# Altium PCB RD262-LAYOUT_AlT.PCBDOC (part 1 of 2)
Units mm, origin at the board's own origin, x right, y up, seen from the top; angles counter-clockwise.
Board outline 110 x 64.13 mm, 4 copper layers (TOP, Mid-Layer 1, Mid-Layer 2, BOTTOM), stack 0.711 mm thick; 50 components, 28 nets, 252 pads, 303 vias.
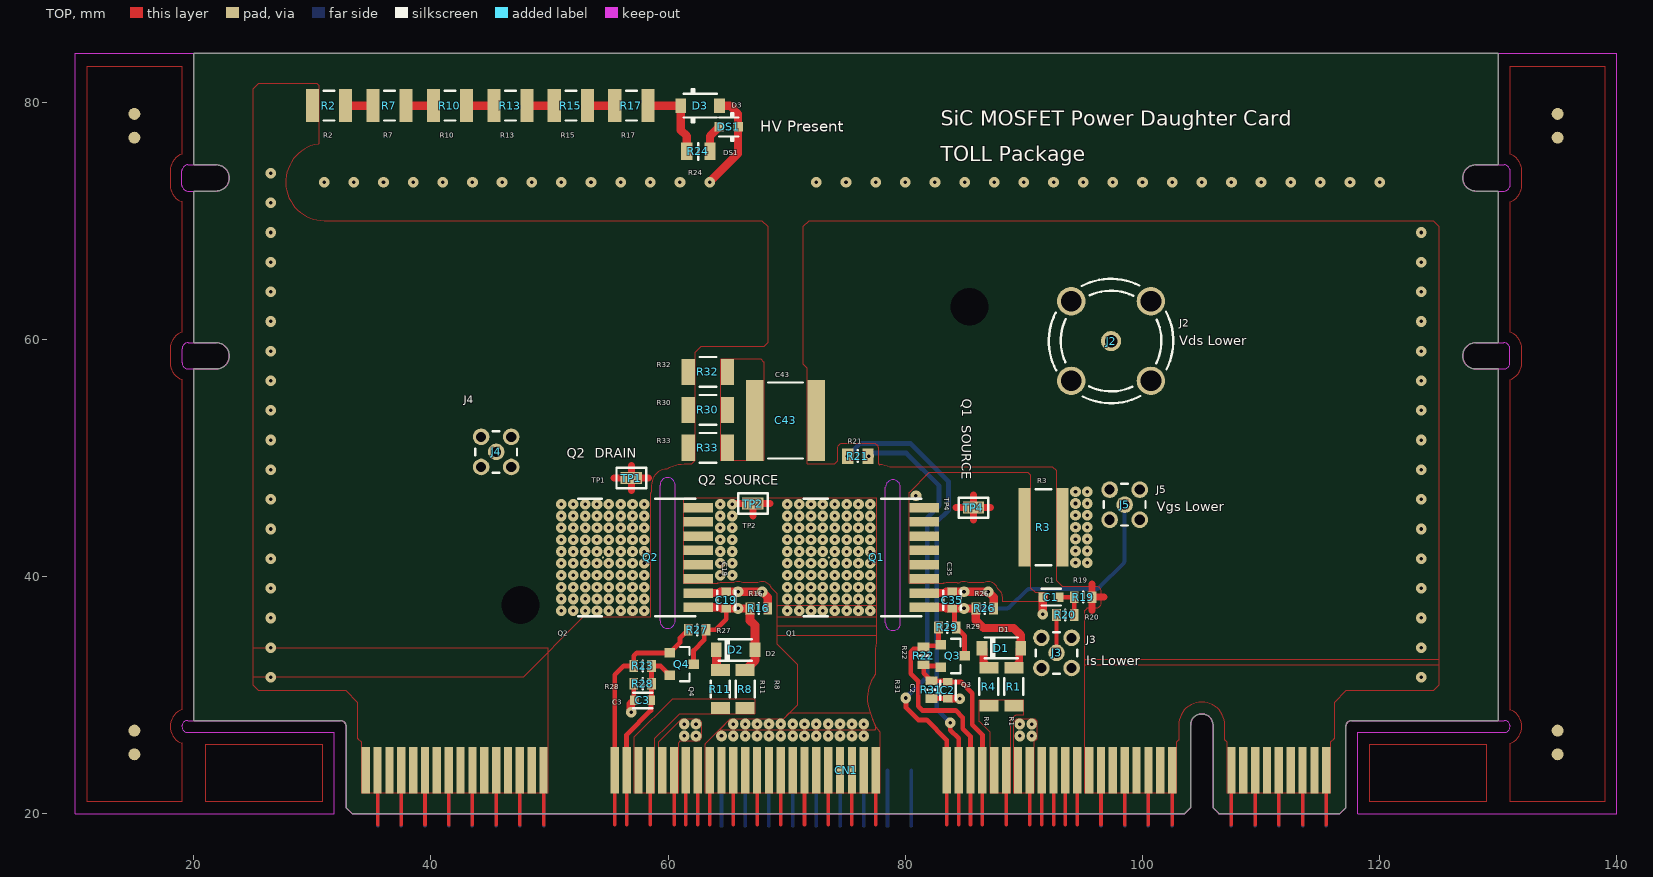
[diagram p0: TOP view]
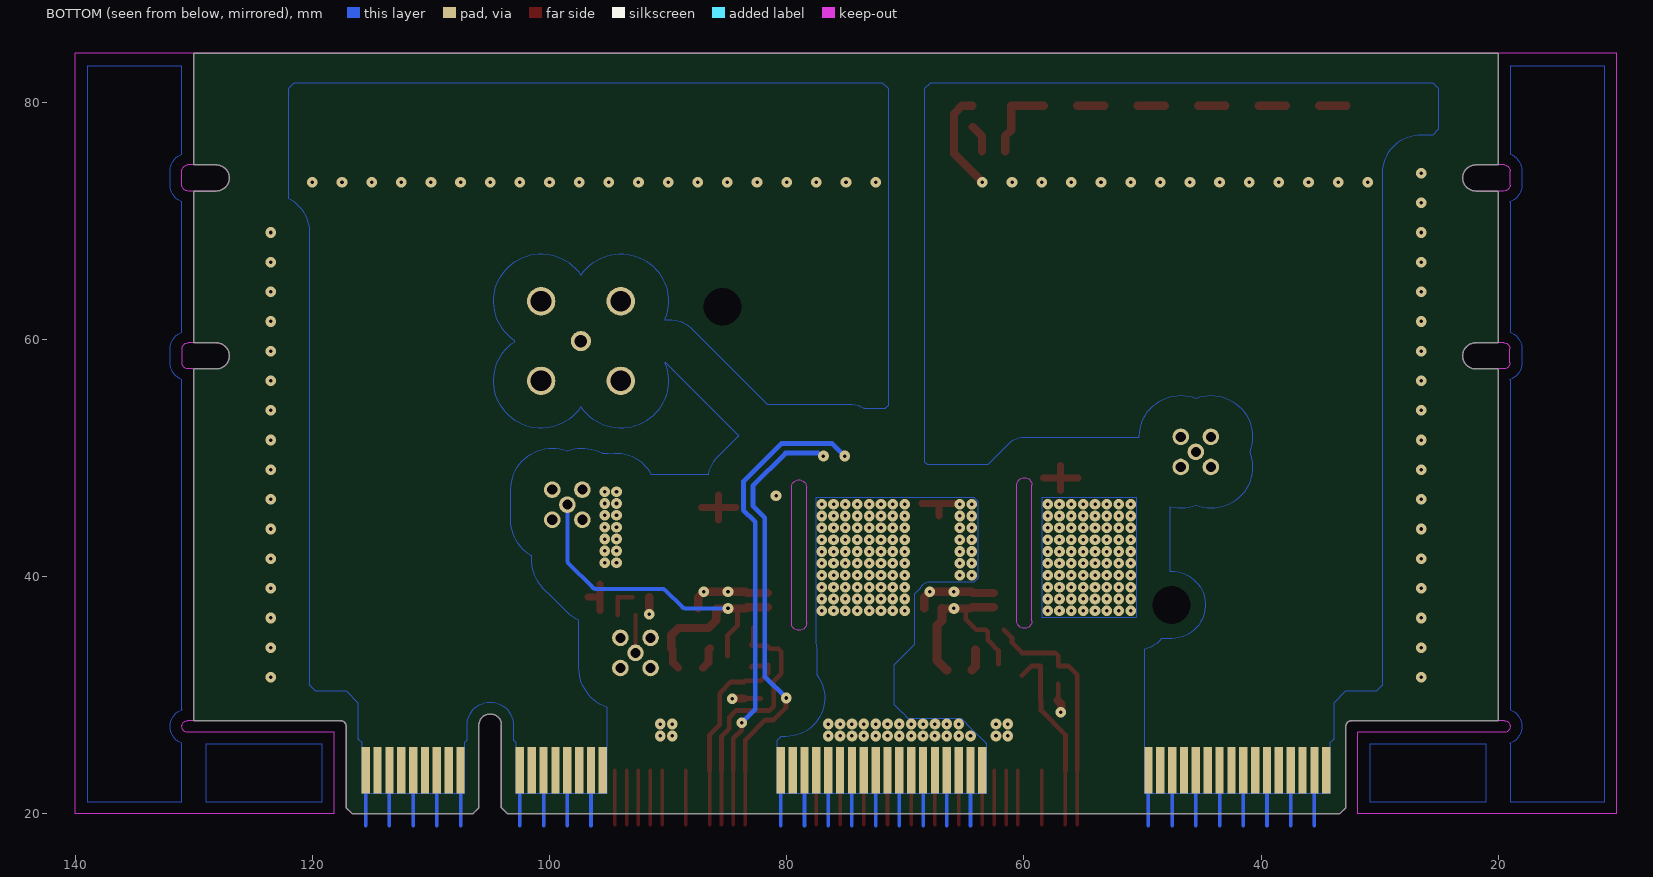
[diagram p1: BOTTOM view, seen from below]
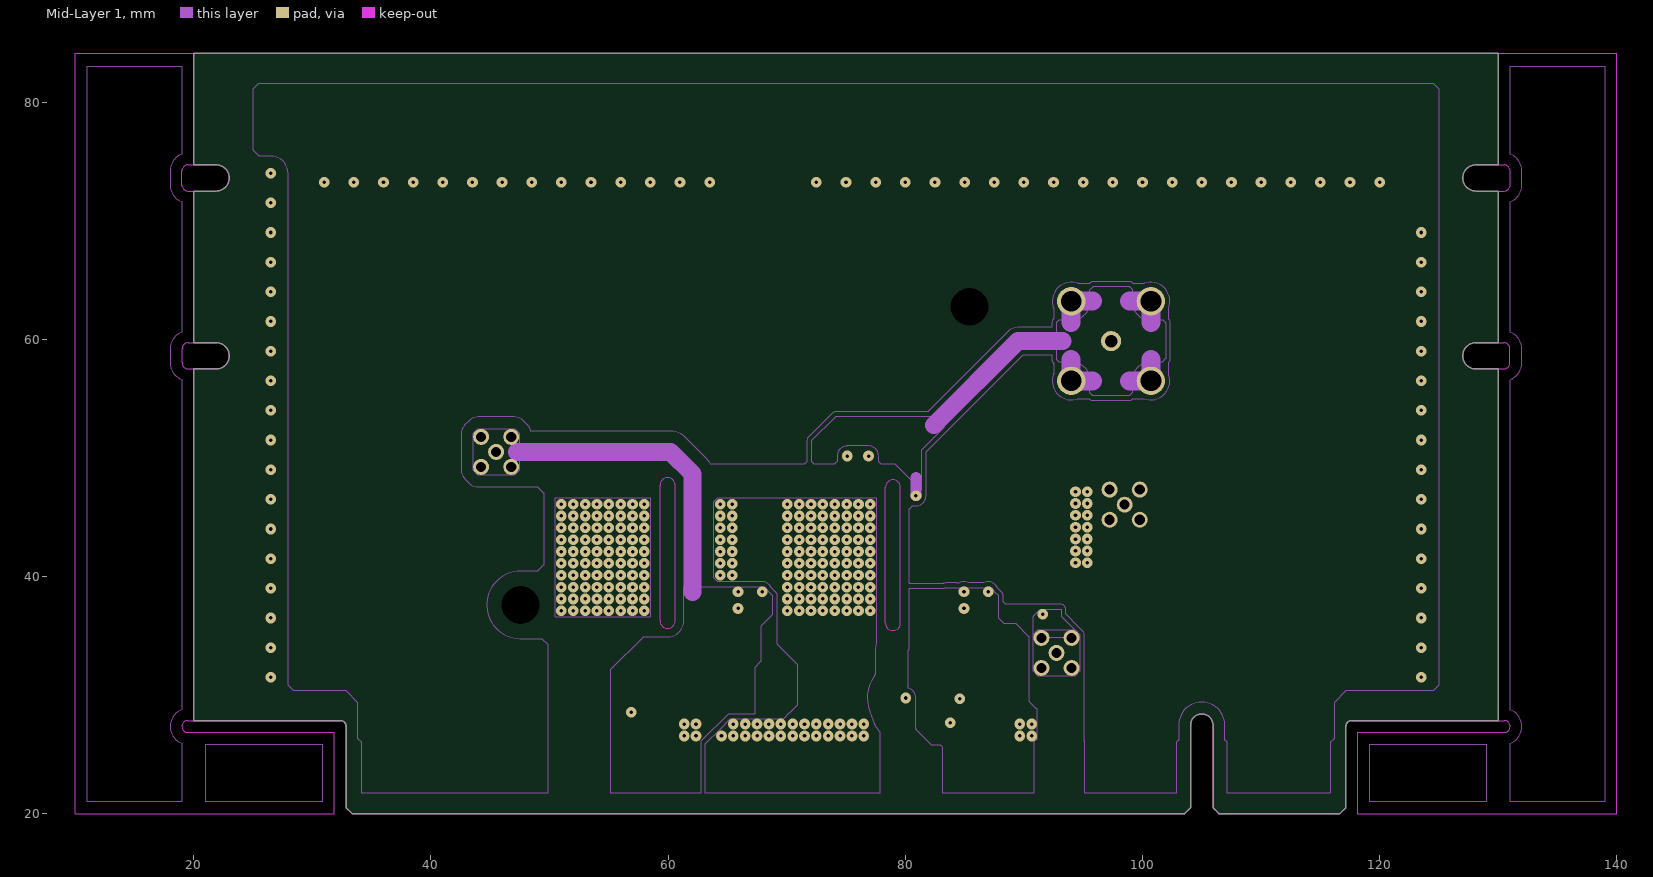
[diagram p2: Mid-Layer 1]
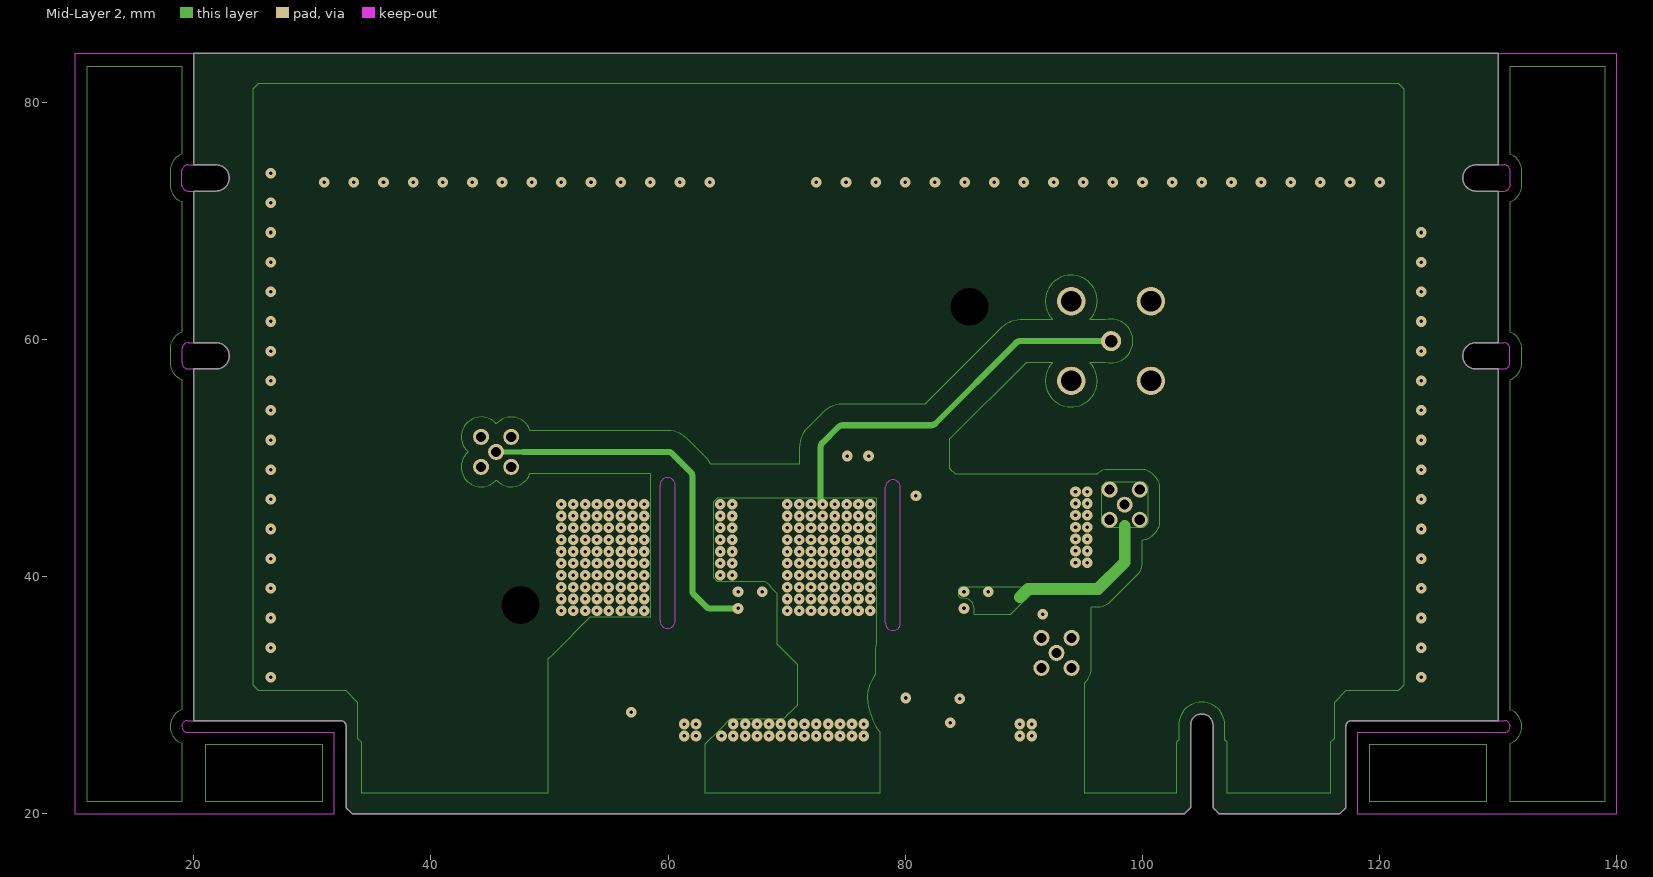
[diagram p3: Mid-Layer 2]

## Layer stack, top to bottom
Top Solder: solder mask 0.0102, Solder Resist, Dk 3.5
TOP: signal copper (thickness not stored)
Mid-Layer 1: signal copper 0.0356
Dielectric2: dielectric 0.32, FR-4, Dk 4.8
Mid-Layer 2: signal copper 0.0356
Dielectric3: dielectric 0.32, FR-4, Dk 4.8
BOTTOM: signal copper (thickness not stored)
Bottom Solder: solder mask 0.0102, Solder Resist, Dk 3.5

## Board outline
33.35,20 32.85,20.5 32.85,27.35 ccw(c32.35,27.35) 32.35,27.85 20,27.85 20,57.5 21.9,57.5 ccw(c21.9,58.6) 23,58.6 ccw(c21.9,58.6) 21.9,59.7 20,59.7 20,72.5 21.9,72.5 ccw(c21.9,73.6) 23,73.6 ccw(c21.9,73.6) 21.9,74.7 20,74.7 20,84.125 130,84.125 130,74.7 128.1,74.7 ccw(c128.1,73.6) 127,73.6 ccw(c128.1,73.6) 128.1,72.5 130,72.5 130,59.7 128.1,59.7 ccw(c128.1,58.6) 127,58.6 ccw(c128.1,58.6) 128.1,57.5 130,57.5 130,27.85 117.65,27.85 ccw(c117.65,27.35) 117.15,27.35 117.15,20.5 116.65,20 106.45,20 105.95,20.5 105.95,27.45 ccw(c105,27.45) 105,28.4 ccw(c105,27.45) 104.05,27.45 104.05,20.5 103.55,20

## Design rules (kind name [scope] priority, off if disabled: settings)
AssemblyTestPointUsage [All] p0: scope1count=1 scope1_0_kind=Board scope1_0_value=Board scope2count=1 scope2_0_kind=Board scope2_0_value=Board commentlength=0
AssemblyTestpoint [All] p0: scope1count=1 scope1_0_kind=Board scope1_0_value=Board scope2count=1 scope2_0_kind=Board scope2_0_value=Board commentlength=0
Clearance [All] p0: scope1count=1 scope1_0_kind=Board scope1_0_value=Board scope2count=1 scope2_0_kind=Board scope2_0_value=Board commentlength=0 gap=0.3
Clearance [All] p1: gap=0.3 ignorepadtopadclearanceinfootprint=TRUE except(1: Arc-Hole Track-Hole SMDPad-Hole THPad-Hole Via-Hole Fill-Hole Poly-Hole Region-Hole Text-Hole)
ComponentClearance [All] p0: scope1count=1 scope1_0_kind=Board scope1_0_value=Board scope2count=1 scope2_0_kind=Board scope2_0_value=Board commentlength=0 gap=0.254 collisioncheckmode=3
DiffPairsRouting [All] p0: scope1count=1 scope1_0_kind=Board scope1_0_value=Board scope2count=1 scope2_0_kind=Board scope2_0_value=Board commentlength=0
FabricationTestPointUsage [All] p0: scope1count=1 scope1_0_kind=Board scope1_0_value=Board scope2count=1 scope2_0_kind=Board scope2_0_value=Board commentlength=0 valid=0 allowmultiple=FALSE
FabricationTestpoint [All] p0: scope1count=1 scope1_0_kind=Board scope1_0_value=Board scope2count=1 scope2_0_kind=Board scope2_0_value=Board commentlength=0 side=3 testpointundercomponent=TRUE minsize=1.016 maxsize=2.54 preferedsize=1.524 minholesize=0 maxholesize=1.016 preferedholesize=0.813 testpointgrid=0.025
FanoutControl Fanout_Default [All] p0: scope1count=1 scope1_0_kind=Board scope1_0_value=Board scope2count=1 scope2_0_kind=Board scope2_0_value=Board commentlength=30 // Fanout_Default (Default Rule)
FanoutControl Fanout_Small [All] p0 off: scope1count=1 scope1_0_kind=Board scope1_0_value=Board scope2count=1 scope2_0_kind=Board scope2_0_value=Board commentlength=84 // Protel DXP Scope 1 Expression Was: (CompPinCount < 5)   Fanout_Small (Default Rule)
FanoutControl Fanout_SOIC [All] p0 off: scope1count=1 scope1_0_kind=Board scope1_0_value=Board scope2count=1 scope2_0_kind=Board scope2_0_value=Board commentlength=71 // Protel DXP Scope 1 Expression Was: IsSOIC   Fanout_SOIC (Default Rule)
FanoutControl Fanout_LCC [All] p0 off: scope1count=1 scope1_0_kind=Board scope1_0_value=Board scope2count=1 scope2_0_kind=Board scope2_0_value=Board commentlength=69 // Protel DXP Scope 1 Expression Was: IsLCC   Fanout_LCC (Default Rule)
FanoutControl Fanout_BGA [All] p0 off: scope1count=1 scope1_0_kind=Board scope1_0_value=Board scope2count=1 scope2_0_kind=Board scope2_0_value=Board commentlength=69 // Protel DXP Scope 1 Expression Was: IsBGA   Fanout_BGA (Default Rule)
Height [All] p0: scope1count=1 scope1_0_kind=Board scope1_0_value=Board scope2count=1 scope2_0_kind=Board scope2_0_value=Board commentlength=0
HoleSize [All] p0: scope1count=1 scope1_0_kind=Board scope1_0_value=Board scope2count=1 scope2_0_kind=Board scope2_0_value=Board commentlength=0 absolutevalues=TRUE maxlimit=100 minlimit=0.001 maxpercent=80.000 minpercent=20.000
HoleSize [All] p1: absolutevalues=TRUE maxlimit=100 minlimit=0.001 maxpercent=80.000 minpercent=20.000
HoleToHoleClearance [All] p0: scope1count=1 scope1_0_kind=Board scope1_0_value=Board scope2count=1 scope2_0_kind=Board scope2_0_value=Board commentlength=0
HoleToHoleClearance [All] p1: gap=0.5 allowstackedmicrovias=FALSE
LayerPairs [All] p0: scope1count=1 scope1_0_kind=Board scope1_0_value=Board scope2count=1 scope2_0_kind=Board scope2_0_value=Board commentlength=0 enforce=TRUE
MinimumSolderMaskSliver [All] p0: scope1count=1 scope1_0_kind=Board scope1_0_value=Board scope2count=1 scope2_0_kind=Board scope2_0_value=Board commentlength=0
MinimumSolderMaskSliver [All] p1: minsoldermaskwidth=0.1
NetAntennae [All] p0: scope1count=1 scope1_0_kind=Board scope1_0_value=Board scope2count=1 scope2_0_kind=Board scope2_0_value=Board commentlength=0
NetAntennae [All] p1: netantennaetolerance=100
PasteMaskExpansion [All] p0: scope1count=1 scope1_0_kind=Board scope1_0_value=Board scope2count=1 scope2_0_kind=Board scope2_0_value=Board commentlength=0 expansion=0
PlaneClearance [All] p0: scope1count=1 scope1_0_kind=Board scope1_0_value=Board scope2count=1 scope2_0_kind=Board scope2_0_value=Board commentlength=0 clearance=0.001
PlaneClearance [All] p1: clearance=0.001
PlaneConnect [All] p0: scope1count=1 scope1_0_kind=Board scope1_0_value=Board scope2count=1 scope2_0_kind=Board scope2_0_value=Board commentlength=0 planeconnectstyle=Direct reliefexpansion=0.508 reliefentries=4 reliefconductorwidth=0.254 reliefairgap=0.254
PlaneConnect [All] p1: planeconnectstyle=Direct reliefexpansion=0.508 reliefentries=4 reliefconductorwidth=0.254 reliefairgap=0.254
PolygonConnect [All] p0: scope1count=1 scope1_0_kind=Board scope1_0_value=Board scope2count=1 scope2_0_kind=Board scope2_0_value=Board commentlength=0 connectstyle=Direct reliefconductorwidth=0.254 reliefentries=4 polygonreliefangle="90 Angle"
PolygonConnect [All] p1: connectstyle=Direct reliefconductorwidth=0.254 reliefentries=4 polygonreliefangle="90 Angle" airgapwidth=0.254
RoutingCorners [All] p0: scope1count=1 scope1_0_kind=Board scope1_0_value=Board scope2count=1 scope2_0_kind=Board scope2_0_value=Board commentlength=0 cornerstyle=45-Degree minsetback=2.54 maxsetback=2.54
RoutingLayers [All] p0: scope1count=1 scope1_0_kind=Board scope1_0_value=Board scope2count=1 scope2_0_kind=Board scope2_0_value=Board commentlength=0 top layer=Automatic mid layer 1=Automatic mid layer 2=Automatic bottom layer=Automatic
RoutingPriority [All] p0: scope1count=1 scope1_0_kind=Board scope1_0_value=Board scope2count=1 scope2_0_kind=Board scope2_0_value=Board commentlength=0
RoutingTopology [All] p0: scope1count=1 scope1_0_kind=Board scope1_0_value=Board scope2count=1 scope2_0_kind=Board scope2_0_value=Board commentlength=0 topology=Shortest
RoutingVias [All] p0: scope1count=1 scope1_0_kind=Board scope1_0_value=Board scope2count=1 scope2_0_kind=Board scope2_0_value=Board commentlength=0 holewidth=0.1 width=0.1 viastyle="Through Hole" minholewidth=0.001 minwidth=0.001 maxholewidth=100 maxwidth=100
RoutingVias [All] p1: holewidth=0.1 width=0.1 viastyle="Through Hole" minholewidth=0.001 minwidth=0.001 maxholewidth=100 maxwidth=100
ShortCircuit [All] p0: scope1count=1 scope1_0_kind=Board scope1_0_value=Board scope2count=1 scope2_0_kind=Board scope2_0_value=Board commentlength=0 allowed=FALSE
SilkToBoardRegionClearance [All] p0: scope1count=1 scope1_0_kind=Board scope1_0_value=Board scope2count=1 scope2_0_kind=Board scope2_0_value=Board commentlength=0
SilkToSilkClearance [All] p0: scope1count=1 scope1_0_kind=Board scope1_0_value=Board scope2count=1 scope2_0_kind=Board scope2_0_value=Board commentlength=0
SilkToSilkClearance [All] p1: silktosilkclearance=0.001
SilkToSolderMaskClearance [All] p0 off: scope1count=1 scope1_0_kind=Board scope1_0_value=Board scope2count=1 scope2_0_kind=Board scope2_0_value=Board commentlength=44 // Protel DXP Scope 1 Expression Was: IsPad
SilkToSolderMaskClearance [IsPad] p1: minsilkscreentomaskgap=0.05 clearancetoexposedcopper=TRUE
SolderMaskExpansion [All] p0: scope1count=1 scope1_0_kind=Board scope1_0_value=Board scope2count=1 scope2_0_kind=Board scope2_0_value=Board commentlength=0 expansion=0.001
SolderMaskExpansion [All] p1: expansion=0.001
UnRoutedNet [All] p0: scope1count=1 scope1_0_kind=Board scope1_0_value=Board scope2count=1 scope2_0_kind=Board scope2_0_value=Board commentlength=0
UnpouredPolygon [All] p0: scope1count=1 scope1_0_kind=Board scope1_0_value=Board scope2count=1 scope2_0_kind=Board scope2_0_value=Board commentlength=0
Width [All] p0: scope1count=1 scope1_0_kind=Board scope1_0_value=Board scope2count=1 scope2_0_kind=Board scope2_0_value=Board commentlength=0 maxlimit=1000 minlimit=2539.975 preferedwidth=0
Width [All] p1: maxlimit=1000 minlimit=2539.975 preferedwidth=0 toplayer_minwidth=0 midlayer1_minwidth=0 midlayer2_minwidth=0 bottomlayer_minwidth=0 minimp=50.000000 maximp=50.000000 favimp=50.000000
22 further rules are at their usual default settings.

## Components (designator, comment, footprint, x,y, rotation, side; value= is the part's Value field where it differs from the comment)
C1 "Chip1608_GS_9" Chip1608_GS_9 92.3,38.25 r180 top
C2 "Chip1608_GS_9" Chip1608_GS_9 83.6,30.4 r270 top
C3 "Chip1608_GS_9" Chip1608_GS_9 57.85,29.55 r180 top
C19 "Chip1608_GS_9" Chip1608_GS_9 64.9,38 r90 top
C35 "Chip1608_GS_9" Chip1608_GS_9 83.95,38 r90 top
C43 "Chip5664_KT_1" Chip5664_KT_1 69.9,53.15 r0 top
cam1 "Drawing-Flame_4x120" Drawing-Flame_4x120 15,-40 r0 top
cam2 "PCB-Name_4x70" PCB-Name_4x70 10,5 r0 top
CN1 "CN_E_EdgeCN_MOD-PWR-MM-L-L_GS" CN_E_EdgeCN_MOD-PWR-MM-L-L_GS 105,20 r0 top
D1 "DI_S_SOD123FL_2_MCC_A1" DI_S_SOD123FL_2_MCC_A1 88.1,33.95 r180 top
D2 "DI_S_SOD123FL_2_MCC_A1" DI_S_SOD123FL_2_MCC_A1 65.7,33.8 r180 top
D3 "DI_S_SOD123FL_2_OS_A2" DI_S_SOD123FL_2_OS_A2 62.7,79.7 r0 top
DS1 "LD_S_150060**75020_WE_A1" LD_S_150060**75020_WE_A1 65.1,77.9 r180 top
J2 "CN_I_73100-0133_MX_A1" CN_I_73100-0133_MX_A1 97.35,59.85 r45 top
J3 "CN_I_73415-1471_MX_A1" CN_I_73415-1471_MX_A1 92.75,33.55 r0 top
J4 "CN_I_73415-1471_MX_A1" CN_I_73415-1471_MX_A1 45.5,50.5 r0 top
J5 "CN_I_73415-1471_MX_A1" CN_I_73415-1471_MX_A1 98.5,46.05 r0 top
Q1 "TR_S_TOLL_8_1.2_TS_1" TR_S_TOLL_8_1.2_TS_1 81.95,41.6 r90 top
Q2 "TR_S_TOLL_8_1.2_TS_1" TR_S_TOLL_8_1.2_TS_1 62.9,41.6 r90 top
Q3 "TR_S_SOT23_3_0.915_DI_B1" TR_S_SOT23_3_0.915_DI_B1 84,33.3 r270 top
Q4 "TR_S_SOT23_3_0.915_DI_B1" TR_S_SOT23_3_0.915_DI_B1 61.15,32.6 r270 top
R1 "R_S_RMCF1206_SPE_1" R_S_RMCF1206_SPE_1 89.15,30.7 r90 top
R2 "R_S_CRCW1210_VS_1" R_S_CRCW1210_VS_1 31.4,79.7 r0 top
R3 "R_S_PRL3264_GS_1" R_S_PRL3264_GS_1 91.65,44.15 r0 top
R4 "R_S_RMCF1206_SPE_1" R_S_RMCF1206_SPE_1 87.05,30.7 r90 top
R7 "R_S_CRCW1210_VS_1" R_S_CRCW1210_VS_1 36.5,79.7 r0 top
R8 "R_S_RMCF1206_SPE_1" R_S_RMCF1206_SPE_1 66.5,30.5 r90 top
R10 "R_S_CRCW1210_VS_1" R_S_CRCW1210_VS_1 41.6,79.7 r0 top
R11 "R_S_RMCF1206_SPE_1" R_S_RMCF1206_SPE_1 64.4,30.5 r90 top
R13 "R_S_CRCW1210_VS_1" R_S_CRCW1210_VS_1 46.7,79.7 r0 top
R15 "R_S_CRCW1210_VS_1" R_S_CRCW1210_VS_1 51.8,79.7 r0 top
R16 "R_S_CRCW0603_VS_1" R_S_CRCW0603_VS_1 67.65,37.3 r0 top
R17 "R_S_CRCW1210_VS_1" R_S_CRCW1210_VS_1 56.9,79.7 r0 top
R19 "R_S_CRCW0603_VS_1" R_S_CRCW0603_VS_1 95,38.25 r0 top
R20 "R_S_CRCW0603_VS_1" R_S_CRCW0603_VS_1 93.5,36.75 r0 top
R21 "R_S_NTCS0603E_VS_1" R_S_NTCS0603E_VS_1 76,50.15 r0 top
R22 "R_S_CRCW0603_VS_1" R_S_CRCW0603_VS_1 81.55,33.3 r270 top
R23 "R_S_CRCW0603_VS_1" R_S_CRCW0603_VS_1 57.85,32.45 r0 top
R24 "R_S_CRCW0805_VS_1" R_S_CRCW0805_VS_1 62.55,75.85 r0 top
R26 "R_S_CRCW0603_VS_1" R_S_CRCW0603_VS_1 86.7,37.3 r0 top
R27 "R_S_CRCW0603_VS_1" R_S_CRCW0603_VS_1 62.45,35.5 r180 top
R28 "R_S_CRCW0603_VS_1" R_S_CRCW0603_VS_1 57.85,30.95 r180 top
R29 "R_S_CRCW0603_VS_1" R_S_CRCW0603_VS_1 83.55,35.7 r180 top
R30 "Chip3225_GS_5" Chip3225_GS_5 63.35,54.05 r0 top
R31 "R_S_CRCW0603_VS_1" R_S_CRCW0603_VS_1 82.2,30.45 r270 top
R32 "Chip3225_GS_5" Chip3225_GS_5 63.35,57.25 r0 top
R33 "Chip3225_GS_5" Chip3225_GS_5 63.35,50.85 r0 top
TP1 "TP_S_S2761-46R_HW_1" TP_S_S2761-46R_HW_1 56.9,48.3 r0 top
TP2 "TP_S_S2761-46R_HW_1" TP_S_S2761-46R_HW_1 67.15,46.15 r0 top
TP4 "TP_S_S2761-46R_HW_1" TP_S_S2761-46R_HW_1 85.75,45.8 r0 top

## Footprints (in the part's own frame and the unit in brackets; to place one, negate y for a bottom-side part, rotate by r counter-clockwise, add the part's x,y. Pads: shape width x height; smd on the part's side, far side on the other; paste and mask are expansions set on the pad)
Chip1608_GS_9 [mm] "KC00080BKP"
  rect 0.7x0.8 smd paste-0.9 mask+0: 1(-0.7,0) 2(0.7,0)
  silkscreen extent -0.8,-0.7 0.8,0.7
Chip3225_GS_5 [mm] "KC00080BKP"
  rect 1.1x2.2 smd paste-2.3 mask+0: 1(-1.65,0) 2(1.65,0)
  silkscreen extent -0.7,-1.25 0.7,1.25
Chip5664_KT_1 [mm] "KC00080BKP"
  rect 1.5x6.8 smd paste-6.9 mask+0: 1(-2.6,0) 2(2.6,0)
  silkscreen extent -1.45,-3.2 1.45,3.2
CN_E_EdgeCN_MOD-PWR-MM-L-L_GS [mm] "KC00080BKP"
  rect 0.7x3.91 smd paste-3.91 mask+0: A2(10.5,3.645) A3(9.5,3.645) A4(8.5,3.645) A5(7.5,3.645) A6(6.5,3.645) A7(5.5,3.645) A8(4.5,3.645) A9(3.5,3.645) A10(2.5,3.645) A13(-2.5,3.645) A14(-3.5,3.645) A15(-4.5,3.645) A16(-5.5,3.645) A17(-6.5,3.645) A18(-7.5,3.645) A19(-8.5,3.645) A20(-9.5,3.645) A21(-10.5,3.645) A22(-11.5,3.645) A23(-12.5,3.645) A24(-13.5,3.645) A25(-14.5,3.645) A26(-15.5,3.645) A27(-16.5,3.645) A28(-17.5,3.645) A29(-18.5,3.645) A30(-19.5,3.645) A31(-20.5,3.645) A32(-21.5,3.645) A38(-27.5,3.645) A39(-28.5,3.645) A40(-29.5,3.645) A41(-30.5,3.645) A42(-31.5,3.645) A43(-32.5,3.645) A44(-33.5,3.645) A45(-34.5,3.645) A46(-35.5,3.645) A47(-36.5,3.645) A48(-37.5,3.645) A49(-38.5,3.645) A50(-39.5,3.645) A51(-40.5,3.645) A52(-41.5,3.645) A53(-42.5,3.645) A54(-43.5,3.645) A55(-44.5,3.645) A56(-45.5,3.645) A57(-46.5,3.645) A58(-47.5,3.645) A59(-48.5,3.645) A60(-49.5,3.645) A66(-55.5,3.645) A67(-56.5,3.645) A68(-57.5,3.645) A69(-58.5,3.645) A70(-59.5,3.645) A71(-60.5,3.645) A72(-61.5,3.645) A73(-62.5,3.645) A74(-63.5,3.645) A75(-64.5,3.645) A76(-65.5,3.645) A77(-66.5,3.645) A78(-67.5,3.645) A79(-68.5,3.645) A80(-69.5,3.645) A81(-70.5,3.645)
  rect 0.7x3.91 smd far side paste-3.91 mask+0: B2(10.5,3.645) B3(9.5,3.645) B4(8.5,3.645) B5(7.5,3.645) B6(6.5,3.645) B7(5.5,3.645) B8(4.5,3.645) B9(3.5,3.645) B10(2.5,3.645) B13(-2.5,3.645) B14(-3.5,3.645) B15(-4.5,3.645) B16(-5.5,3.645) B17(-6.5,3.645) B18(-7.5,3.645) B19(-8.5,3.645) B20(-9.5,3.645) B35(-24.5,3.645) B36(-25.5,3.645) B37(-26.5,3.645) B38(-27.5,3.645) B39(-28.5,3.645) B40(-29.5,3.645) B41(-30.5,3.645) B42(-31.5,3.645) B43(-32.5,3.645) B44(-33.5,3.645) B45(-34.5,3.645) B46(-35.5,3.645) B47(-36.5,3.645) B48(-37.5,3.645) B49(-38.5,3.645) B50(-39.5,3.645) B51(-40.5,3.645) B52(-41.5,3.645) B66(-55.5,3.645) B67(-56.5,3.645) B68(-57.5,3.645) B69(-58.5,3.645) B70(-59.5,3.645) B71(-60.5,3.645) B72(-61.5,3.645) B73(-62.5,3.645) B74(-63.5,3.645) B75(-64.5,3.645) B76(-65.5,3.645) B77(-66.5,3.645) B78(-67.5,3.645) B79(-68.5,3.645) B80(-69.5,3.645) B81(-70.5,3.645)
CN_I_73100-0133_MX_A1 [mm] "KC00080BKP"
  round 1.7 hole 1.05 paste-1.8 mask+0: P(0,0)
  round 2.4 hole 1.75 paste-2.5 mask+0: S1(0,-4.75) S2(4.75,0) S3(0,4.75) S4(-4.75,0)
  silkscreen extent -5.02,-5.02 5.02,5.02
CN_I_73415-1471_MX_A1 [mm] "KC00080BKP"
  round 1.4 / inner round 1.35 / far side round 1.4 hole 0.85 paste-1.5 mask+0: P(0,0) S1(-1.27,-1.27) S2(1.27,-1.27) S3(1.27,1.27) S4(-1.27,1.27)
  silkscreen extent -1.76,-1.75 1.76,1.76
DI_S_SOD123FL_2_MCC_A1 [mm] "KC00080BKP"
  rect 0.91x1.22 smd paste-1.32 mask+0: A(-1.635,0) K(1.635,0)
  silkscreen extent -1.4,-0.9 1.4,0.85
DI_S_SOD123FL_2_OS_A2 [mm] "KC00080BKP"
  rect 0.91x1.22 smd paste-1.32 mask+0: A(1.635,0) K(-1.635,0)
  silkscreen extent -1.4,-1.4 1.4,1.4
Drawing-Flame_4x120 [mm] "KC00080BKP"
LD_S_150060**75020_WE_A1 [mm] "KC00080BKP"
  rect 0.8x0.8 smd paste-0.9 mask+0: A(0.8,0) K(-0.8,0)
  silkscreen extent -0.8,-1.15 0.8,1.15
PCB-Name_4x70 [mm] "KC00080BKP"
R_S_CRCW0603_VS_1 [mm] "KC00080BKP"
  rect 0.75x1 smd paste-1.1 mask+0: 1(-0.75,0) 2(0.75,0)
  silkscreen extent 0,-0.45 0,0.45
R_S_CRCW0805_VS_1 [mm] "KC00080BKP"
  rect 0.95x1.45 smd paste-1.55 mask+0: 1(-0.975,0) 2(0.975,0)
  silkscreen extent 0,-0.7 0,0.7
R_S_CRCW1210_VS_1 [mm] "KC00080BKP"
  rect 1.1x2.8 smd paste-2.9 mask+0: 1(-1.4,0) 2(1.4,0)
  silkscreen extent -0.45,-1.25 0.45,1.25
R_S_NTCS0603E_VS_1 [mm] "KC00080BKP"
  rect 0.95x1.3 smd paste-1.3 mask+0: 1(-0.85,0) 2(0.85,0)
  silkscreen extent 0,-0.5 0,0.5
R_S_PRL3264_GS_1 [mm] "KC00080BKP"
  rect 1x6.6 smd paste-6.7 mask+0: 1(-1.6,0) 2(1.6,0)
  silkscreen extent -0.65,-3.2 0.65,3.2
R_S_RMCF1206_SPE_1 [mm] "KC00080BKP"
  rect 1x1.6 smd paste-1.7 mask+0: 1(-1.6,0) 2(1.6,0)
  silkscreen extent -0.7,-0.8 0.7,0.8
TP_S_S2761-46R_HW_1 [mm] "KC00080BKP"
  rect 1.8x1 smd paste-1.9 mask+0: 1(0,0)
  silkscreen extent -1.25,-0.85 1.25,0.85
TR_S_SOT23_3_0.915_DI_B1 [mm] "KC00080BKP"
  rect 0.8x0.9 smd paste-1 mask+0: D(0,1) G(-0.95,-1) S(0.95,-1)
  silkscreen extent -1.45,-0.65 1.45,0.65
TR_S_TOLL_8_1.2_TS_1 [mm] "KC00080BKP"
  rect 0.8x2.5 smd paste-2.6 mask+0: 1(-4.2,0.35) 2(-3,0.35) 3(-1.8,0.35) 4(-0.6,0.35) 5(0.6,0.35) 6(1.8,0.35) 7(3,0.35) 8(4.2,0.35)
  round 0.178 smd paste-0.178 mask+0: 9(0,8.4)
  silkscreen extent -4.95,0.6 4.95,10.5

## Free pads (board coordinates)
  round 1 smd paste-2 mask+0: ""(15,25) ""(15,27) ""(15,77) ""(15,79) ""(135,25) ""(135,27) ""(135,77) ""(135,79)
  round 0 hole 2 unplated paste-2.4 mask+0: ""(15,35) ""(15,70) ""(135,35) ""(135,60)
  round 0 hole 3.2 unplated paste-3.6 mask+0: ""(47.55,37.6) ""(85.4,62.74)

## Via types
v1: diameter 0.9, hole 0.3, TOP to BOTTOM, tented both sides, 303 vias

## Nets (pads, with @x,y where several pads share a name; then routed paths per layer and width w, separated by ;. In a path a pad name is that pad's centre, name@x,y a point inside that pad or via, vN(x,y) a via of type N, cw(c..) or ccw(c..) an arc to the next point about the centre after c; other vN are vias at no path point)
0VA: C2.2 C35.2 CN1.A25 CN1.A26 J5.S1 J5.S2 J5.S3 J5.S4 Q1.2 R26.2 R31.2 | length 27.1
  TOP w0.3: 90.5,19.05 CN1.A25@90.5,23.645
  TOP w0.4: R31.2@82.2,29.7 C2.2@83.6,29.7
  TOP w0.7: Q1.2@81.6,38.6 83.35,38.6 83.45,38.7 C35.2@83.95,38.7 v1(84.95,38.7) v1(87,38.7) 87.45,38.25 R26.2@87.45,37.3 ; C2.2@83.6,29.7 v1(84.6,29.7)
  Mid-Layer 2 w1: 89.65,38.25 90.35,38.95 96.25,38.95 98.5,41.2 98.5,44.25
  other v1: 89.65,26.55 90.65,26.55 89.65,27.55 90.65,27.55
0VB: C3.2 C19.2 CN1.A55 CN1.A56 J4.S1 J4.S2 J4.S3 J4.S4 Q2.2 R16.2 R28.2 | length 39.7
  TOP w0.3: 60.5,19.05 CN1.A55@60.5,23.645
  TOP w0.4: R28.2@57.1,30.95 57.1,29.6 C3.2@57.15,29.55
  TOP w0.7: v1(56.9,28.55) 56.85,28.6 56.85,29.25 C3.2@57.15,29.55 ; Q2.2@62.55,38.6 64.3,38.6 64.4,38.7 C19.2@64.9,38.7 v1(65.9,38.7) v1(67.95,38.7) 68.4,38.25 R16.2@68.4,37.3
  Mid-Layer 1 w1.5: 47.25,50.5 60.2,50.5 62.05,48.65 62.05,38.7
  other v1: 61.35,26.55 62.35,26.55 61.35,27.55 62.35,27.55
HS_GATE: CN1.A57 CN1.A58 R8.1 R11.1 | length 4.6
  TOP w0.3: 58.5,19.05 CN1.A57@58.5,23.645
LS_GATE: CN1.A27 CN1.A28 R1.1 R4.1 | length 4.6
  TOP w0.3: 88.5,19.05 CN1.A27@88.5,23.645
MIDPOINT: CN1.A38 CN1.A39 CN1.A40 CN1.A41 CN1.A42 CN1.A43 CN1.A44 CN1.A45 CN1.A46 CN1.A47 CN1.A48 CN1.A49 CN1.A50 CN1.A51 CN1.A52 CN1.B35 CN1.B36 CN1.B37 CN1.B38 CN1.B39 CN1.B40 CN1.B41 CN1.B42 CN1.B43 CN1.B44 CN1.B45 CN1.B46 CN1.B47 CN1.B48 CN1.B49 CN1.B50 CN1.B51 CN1.B52 J2.P Q1.9 Q2.3 Q2.4 Q2.5 Q2.6 Q2.7 Q2.8 TP2.1 | length 115.8
  TOP w0.3: 63.5,19.05 CN1.A52@63.5,23.645 ; 65.5,19.05 CN1.A50@65.5,23.645 ; 67.5,19.05 CN1.A48@67.5,23.645 ; 69.5,19.05 CN1.A46@69.5,23.645 ; 71.5,19.05 CN1.A44@71.5,23.645 ; 73.5,19.05 CN1.A42@73.5,23.645 ; 75.5,19.05 CN1.A40@75.5,23.645 ; 77.5,19.05 CN1.A38@77.5,23.645
  TOP w0.6: v1@65.7,46.15 TP2.1@67.15,46.15 ; 67.15,45.1 TP2.1@67.15,46.15 ; 68.6,46.15 TP2.1@67.15,46.15
  Mid-Layer 2 w0.51: v1(73.05,46.1) 72.85,46.1 72.85,50.893 cw(c73.35,50.893) 72.996,51.246 74.354,52.604 cw(c74.707,52.25) 74.707,52.75 82.193,52.75 ccw(c82.193,53.25) 82.546,52.896 89.354,59.704 cw(c89.707,59.35) 89.707,59.85 J2.P@97.35,59.85
  BOTTOM w0.3: 64.5,19 CN1.B51@64.5,23.645 CN1.B51@64.5,23.65 ; 66.5,19 CN1.B49@66.5,23.645 CN1.B49@66.5,23.65 ; 68.5,19 CN1.B47@68.5,23.645 CN1.B47@68.5,23.65 ; 70.5,19 CN1.B45@70.5,23.645 CN1.B45@70.5,23.65 ; 72.5,19 CN1.B43@72.5,23.645 CN1.B43@72.5,23.65 ; 74.5,19 CN1.B41@74.5,23.645 CN1.B41@74.5,23.65 ; 76.5,19 CN1.B39@76.5,23.645 CN1.B39@76.5,23.65 ; 78.5,19 CN1.B37@78.5,23.645 CN1.B37@78.5,23.65 ; 80.5,19 CN1.B35@80.5,23.645 CN1.B35@80.5,23.65
  other v1: 64.5,26.55 65.5,26.55 66.5,26.55 67.5,26.55 68.5,26.55 69.5,26.55 70.5,26.55 71.5,26.55 72.5,26.55 73.5,26.55 74.5,26.55 75.5,26.55 76.5,26.55 65.5,27.55 66.5,27.55 67.5,27.55 68.5,27.55 69.5,27.55 70.5,27.55 71.5,27.55 72.5,27.55 73.5,27.55 74.5,27.55 75.5,27.55 76.5,27.55 70.05,37.1 71.05,37.1 72.05,37.1 73.05,37.1 74.05,37.1 75.05,37.1 76.05,37.1 77.05,37.1 70.05,38.1 71.05,38.1 72.05,38.1 73.05,38.1 74.05,38.1 75.05,38.1 76.05,38.1 77.05,38.1 70.05,39.1 71.05,39.1 72.05,39.1 73.05,39.1 74.05,39.1 75.05,39.1 76.05,39.1 77.05,39.1 64.4,40.1 65.4,40.1 70.05,40.1 71.05,40.1 72.05,40.1 73.05,40.1 74.05,40.1 75.05,40.1 76.05,40.1 77.05,40.1 64.4,41.1 65.4,41.1 70.05,41.1 71.05,41.1 72.05,41.1 73.05,41.1 74.05,41.1 75.05,41.1 76.05,41.1 77.05,41.1 64.4,42.1 65.4,42.1 70.05,42.1 71.05,42.1 72.05,42.1 73.05,42.1 74.05,42.1 75.05,42.1 76.05,42.1 77.05,42.1 64.4,43.1 65.4,43.1 70.05,43.1 71.05,43.1 72.05,43.1 73.05,43.1 74.05,43.1 75.05,43.1 76.05,43.1 77.05,43.1 64.4,44.1 65.4,44.1 70.05,44.1 71.05,44.1 72.05,44.1 73.05,44.1 74.05,44.1 75.05,44.1 76.05,44.1 77.05,44.1 64.4,45.1 65.4,45.1 70.05,45.1 71.05,45.1 72.05,45.1 73.05,45.1 74.05,45.1 75.05,45.1 76.05,45.1 77.05,45.1 64.4,46.1 65.4,46.1 70.05,46.1 71.05,46.1 72.05,46.1 74.05,46.1 75.05,46.1 76.05,46.1 77.05,46.1
N12548643: CN1.A32 R21.2 | length 38.8
  TOP w0.3: 83.5,19.05 CN1.A32@83.5,23.645
  TOP w0.4: v1(80.05,29.75) 80.05,28.95 81.1,27.9 81.8,27.9 83.5,26.2 CN1.A32@83.5,23.645
  BOTTOM w0.4: v1(76.9,50.15) 77.35,50.4 80.1,50.4 82.85,47.65 82.85,45.95 81.85,44.95 81.85,31.55 v1(80.05,29.75)
N12548854: D1.K R4.2 | length 1.9
  TOP w0.65: D1.K@86.465,33.95 86.6,33.815 86.6,32.75 R4.2@87.05,32.3
N12548858: C35.1 D1.A J5.P Q1.1 Q3.D R1.2 R26.1 R29.1 | length 37.1
  TOP w0.4: C35.1@83.95,37.3 84.15,37.1 84.15,35.85 R29.1@84.3,35.7 85,35 Q3.D@85,33.3
  TOP w0.65: R1.2@89.15,32.3 89.6,32.75 89.6,33.815 D1.A@89.735,33.95
  TOP w0.7: Q1.1@81.6,37.4 83.35,37.4 83.45,37.3 C35.1@83.95,37.3 v1(84.95,37.3) R26.1@85.95,37.3 85.95,36.3 86.6,35.65 89.135,35.65 89.735,35.05 D1.A@89.735,33.95
  BOTTOM w0.341: v1(84.95,37.3) 88.493,37.3 ccw(c88.493,37.8) 88.846,37.446 90.204,38.804 cw(c90.557,38.45) 90.557,38.95 96.043,38.95 ccw(c96.043,39.45) 96.396,39.096 98.354,41.054 ccw(c98,41.407) 98.5,41.407 J5.P@98.5,46.05
N12549850: CN1.A30 Q3.G R22.1 R29.2 | length 22.7
  TOP w0.3: 85.5,19.05 CN1.A30@85.5,23.645
  TOP w0.4: R29.2@82.8,35.7 82.8,34.45 Q3.G@83,34.25 82.9,34.15 81.65,34.15 R22.1@81.55,34.05 81.4,33.9 80.7,33.9 80.45,33.65 80.45,31.8 81.1,31.15 81.1,29.05 81.45,28.7 84.25,28.7 84.85,28.1 84.85,27.15 85.5,26.5 CN1.A30@85.5,23.645
N12549899: CN1.A31 R21.1 | length 40.4
  TOP w0.3: 84.5,19.05 CN1.A31@84.5,23.645
  TOP w0.4: v1(83.8,27.65) 83.8,27.05 84.5,26.35 CN1.A31@84.5,23.645
  BOTTOM w0.4: v1(75.1,50.15) 76.15,51.2 80.45,51.2 83.65,48 83.65,45.6 82.65,44.6 82.65,28.8 v1(83.8,27.65)
N12551355: C2.1 CN1.A29 Q3.S R22.2 R31.1 | length 18.5
  TOP w0.3: 86.5,19.05 CN1.A29@86.5,23.645
  TOP w0.4: Q3.S@83,32.35 82.9,32.45 81.65,32.45 R22.2@81.55,32.55 81.55,31.85 R31.1@82.2,31.2 83.5,31.2 C2.1@83.6,31.1 84.7,31.1 85.65,30.15 85.65,27.5 86.5,26.65 CN1.A29@86.5,23.645
N12552242: C19.1 D2.A J4.P Q2.1 Q4.D R8.2 R16.1 R27.1 | length 48.1
  TOP w0.4: Q4.D@62.15,32.6 62.15,33.75 63.05,34.65 63.05,35.35 R27.1@63.2,35.5 64,35.5 64.9,36.4 C19.1@64.9,37.3
  TOP w0.7: Q2.1@62.55,37.4 64.4,37.4 64.5,37.3 C19.1@64.9,37.3 v1(65.9,37.3) R16.1@66.9,37.3
  TOP w0.75: R8.2@66.5,32.1 67.335,32.935 D2.A@67.335,33.8 67.335,35.865 66.9,36.3 R16.1@66.9,37.3
  Mid-Layer 2 w0.4: J4.P@45.5,50.5 47.75,50.5
  Mid-Layer 2 w0.51: 47.75,50.5 59.993,50.5 ; 59.993,50.5 cw(c59.993,50) 60.346,50.354 61.904,48.796 cw(c61.55,48.443) 62.05,48.443 62.05,38.807 ccw(c62.55,38.807) 62.196,38.454 63.204,37.446 ccw(c63.557,37.8) 63.557,37.3 v1(65.9,37.3)
N12552318: D2.K R11.2 | length 1.8
  TOP w0.75: D2.K@64.065,33.8 64.065,32.435 R11.2@64.4,32.1
N12552490: CN1.A60 Q4.G R23.1 R27.2 | length 21.2
  TOP w0.3: 55.5,19.05 CN1.A60@55.5,23.645
  TOP w0.4: CN1.A60@55.5,23.645 55.5,31.7 56.25,32.45 R23.1@57.1,32.45 57.1,33.3 57.35,33.55 Q4.G@60.15,33.55 61,34.4 61,34.8 R27.2@61.7,35.5
N12552532: C3.1 CN1.A59 Q4.S R23.2 R28.1 | length 16.2
  TOP w0.3: 56.5,19.05 CN1.A59@56.5,23.645
  TOP w0.4: CN1.A59@56.5,23.645 56.5,26.65 58.55,28.7 C3.1@58.55,29.55 58.6,29.6 R28.1@58.6,30.95 R23.2@58.6,32.45 59.35,32.45 Q4.S@60.15,31.65
N12552974: CN1.A66 CN1.A67 CN1.A68 CN1.A69 CN1.A70 CN1.A71 CN1.A72 CN1.A73 CN1.A74 CN1.A75 CN1.A76 CN1.A77 CN1.A78 CN1.A79 CN1.A80 CN1.A81 CN1.B2 CN1.B3 CN1.B4 CN1.B5 CN1.B6 CN1.B7 CN1.B8 CN1.B9 CN1.B10 CN1.B13 CN1.B14 CN1.B15 CN1.B16 CN1.B17 CN1.B18 CN1.B19 CN1.B20 Q2.9 R2.1 R30.1 R32.1 R33.1 TP1.1 | length 83.6
  TOP w0.3: 35.5,19.05 CN1.A80@35.5,23.645 ; 37.5,19.05 CN1.A78@37.5,23.645 ; 39.5,19.05 CN1.A76@39.5,23.645 ; 41.5,19.05 CN1.A74@41.5,23.645 ; 43.5,19.05 CN1.A72@43.5,23.645 ; 45.5,19.05 CN1.A70@45.5,23.645 ; 47.5,19.05 CN1.A68@47.5,23.645 ; 49.5,19.05 CN1.A66@49.5,23.645
  TOP w0.6: 55.45,48.3 TP1.1@56.9,48.3 ; 56.9,47.25 TP1.1@56.9,48.3 ; 56.9,49.35 TP1.1@56.9,48.3 ; 58.35,48.3 TP1.1@56.9,48.3
  BOTTOM w0.3: 96.5,19 CN1.B19@96.5,23.645 CN1.B19@96.5,23.65 ; 98.5,19 CN1.B17@98.5,23.645 CN1.B17@98.5,23.65 ; 100.5,19 CN1.B15@100.5,23.645 CN1.B15@100.5,23.65 ; 102.5,19 CN1.B13@102.5,23.645 CN1.B13@102.5,23.65 ; 107.5,19 CN1.B10@107.5,23.645 CN1.B10@107.5,23.65 ; 109.5,19 CN1.B8@109.5,23.645 CN1.B8@109.5,23.65 ; 111.5,19 CN1.B6@111.5,23.645 CN1.B6@111.5,23.65 ; 113.5,19 CN1.B4@113.5,23.645 CN1.B4@113.5,23.65 ; 115.5,19 CN1.B2@115.5,23.645 CN1.B2@115.5,23.65
  other v1: 26.5,31.5 26.5,34 26.5,36.5 51,37.1 52,37.1 53,37.1 54,37.1 55,37.1 56,37.1 57,37.1 58,37.1 51,38.1 52,38.1 53,38.1 54,38.1 55,38.1 56,38.1 57,38.1 58,38.1 26.5,39 51,39.1 52,39.1 53,39.1 54,39.1 55,39.1 56,39.1 57,39.1 58,39.1 51,40.1 52,40.1 53,40.1 54,40.1 55,40.1 56,40.1 57,40.1 58,40.1 51,41.1 52,41.1 53,41.1 54,41.1 55,41.1 56,41.1 57,41.1 58,41.1 26.5,41.5 51,42.1 52,42.1 53,42.1 54,42.1 55,42.1 56,42.1 57,42.1 58,42.1 51,43.1 52,43.1 53,43.1 54,43.1 55,43.1 56,43.1 57,43.1 58,43.1 26.5,44 51,44.1 52,44.1 53,44.1 54,44.1 55,44.1 56,44.1 57,44.1 58,44.1 51,45.1 52,45.1 53,45.1 54,45.1 55,45.1 56,45.1 57,45.1 58,45.1 51,46.1 52,46.1 53,46.1 54,46.1 55,46.1 56,46.1 57,46.1 58,46.1 26.5,46.5 26.5,49 26.5,51.5 26.5,54 26.5,56.5 26.5,59 26.5,61.5 26.5,64 26.5,66.5 26.5,69 26.5,71.5 72.5,73.25 75,73.25 77.5,73.25 80,73.25 82.5,73.25 85,73.25 87.5,73.25 90,73.25 92.5,73.25 95,73.25 97.5,73.25 100,73.25 102.5,73.25 105,73.25 107.5,73.25 110,73.25 112.5,73.25 115,73.25 117.5,73.25 120,73.25 26.5,74
N12556338: C43.1 R30.2 R32.2 R33.2
N12556342: R2.2 R7.1 | length 2.3
  TOP w0.7: R2.2@32.8,79.7 R7.1@35.1,79.7
N12556346: R7.2 R10.1 | length 2.3
  TOP w0.7: R7.2@37.9,79.7 R10.1@40.2,79.7
N12556350: R10.2 R13.1 | length 2.3
  TOP w0.7: R10.2@43,79.7 R13.1@45.3,79.7
N12556354: R13.2 R15.1 | length 2.3
  TOP w0.7: R13.2@48.1,79.7 R15.1@50.4,79.7
N12556358: R15.2 R17.1 | length 2.3
  TOP w0.7: R15.2@53.2,79.7 R17.1@55.5,79.7
N12556362: D3.K R17.2 R24.1 | length 6.8
  TOP w0.7: R17.2@58.3,79.7 D3.K@61.065,79.7 61.065,77.635 61.575,77.125 R24.1@61.575,75.85
N12556379: DS1.A R24.2 | length 2.4
  TOP w0.7: R24.2@63.525,75.85 63.525,77.125 DS1.A@64.3,77.9
N12556383: C1.2 J2.S1 J2.S2 J2.S3 J2.S4 J3.S1 J3.S2 J3.S3 J3.S4 Q1.3 Q1.4 Q1.5 Q1.6 Q1.7 Q1.8 R3.1 TP4.1 | length 36.3
  TOP w0.6: 84.3,45.8 TP4.1@85.75,45.8 ; 85.75,44.75 TP4.1@85.75,45.8 ; 85.75,46.85 TP4.1@85.75,45.8 ; 87.2,45.8 TP4.1@85.75,45.8
  TOP w0.7: v1(91.6,36.8) C1.2@91.6,38.25
  Mid-Layer 1 w0.9: v1(80.9,46.8) 80.9,48.35
  Mid-Layer 1 w1.5: 82.4,52.75 89.5,59.85 93.25,59.85
  Mid-Layer 1 w1.6: 93.991,58.3 J2.S4@93.991,56.491 95.8,56.491 ; 93.991,61.4 J2.S3@93.991,63.209 95.8,63.209 ; 98.9,56.491 J2.S1@100.709,56.491 100.709,58.3 ; 98.9,63.209 J2.S2@100.709,63.209 100.709,61.4
N12561103: C1.1 R19.1 R20.2 | length 2.7
  TOP w0.4: C1.1@93,38.25 R19.1@94.25,38.25 R20.2@94.25,36.75
N12561502: J3.P R20.1 | length 3.2
  TOP w0.341: J3.P@92.75,33.55 R20.1@92.75,36.75
PGND: C43.2 CN1.A2 CN1.A3 CN1.A4 CN1.A5 CN1.A6 CN1.A7 CN1.A8 CN1.A9 CN1.A10 CN1.A13 CN1.A14 CN1.A15 CN1.A16 CN1.A17 CN1.A18 CN1.A19 CN1.A20 CN1.B66 CN1.B67 CN1.B68 CN1.B69 CN1.B70 CN1.B71 CN1.B72 CN1.B73 CN1.B74 CN1.B75 CN1.B76 CN1.B77 CN1.B78 CN1.B79 CN1.B80 CN1.B81 D3.A DS1.K R3.2 R19.2 | length 90.4
  TOP w0.3: 96.5,19.05 CN1.A19@96.5,23.645 ; 98.5,19.05 CN1.A17@98.5,23.645 ; 100.5,19.05 CN1.A15@100.5,23.645 ; 102.5,19.05 CN1.A13@102.5,23.645 ; 107.5,19.05 CN1.A10@107.5,23.645 ; 109.5,19.05 CN1.A8@109.5,23.645 ; 111.5,19.05 CN1.A6@111.5,23.645 ; 113.5,19.05 CN1.A4@113.5,23.645 ; 115.5,19.05 CN1.A2@115.5,23.645
  TOP w0.6: 95.75,37.15 R19.2@95.75,38.25 ; 95.75,39.35 R19.2@95.75,38.25 ; 96.75,38.25 R19.2@95.75,38.25
  TOP w0.7: v1(63.5,73.25) 65.9,75.65 DS1.K@65.9,77.9 65.9,79 65.2,79.7 D3.A@64.335,79.7
  BOTTOM w0.3: 35.5,19 CN1.B80@35.5,23.645 CN1.B80@35.5,23.65 ; 37.5,19 CN1.B78@37.5,23.645 CN1.B78@37.5,23.65 ; 39.5,19 CN1.B76@39.5,23.645 CN1.B76@39.5,23.65 ; 41.5,19 CN1.B74@41.5,23.645 CN1.B74@41.5,23.65 ; 43.5,19 CN1.B72@43.5,23.645 CN1.B72@43.5,23.65 ; 45.5,19 CN1.B70@45.5,23.645 CN1.B70@45.5,23.65 ; 47.5,19 CN1.B68@47.5,23.645 CN1.B68@47.5,23.65 ; 49.5,19 CN1.B66@49.5,23.645 CN1.B66@49.5,23.65
  other v1: 123.5,31.5 123.5,34 123.5,36.5 123.5,39 94.35,41.15 95.35,41.15 123.5,41.5 94.35,42.15 95.35,42.15 94.35,43.15 95.35,43.15 123.5,44 94.35,44.15 95.35,44.15 94.35,45.15 95.35,45.15 94.35,46.15 95.35,46.15 123.5,46.5 94.35,47.15 95.35,47.15 123.5,49 123.5,51.5 123.5,54 123.5,56.5 123.5,59 123.5,61.5 123.5,64 123.5,66.5 123.5,69 31,73.25 33.5,73.25 36,73.25 38.5,73.25 41,73.25 43.5,73.25 46,73.25 48.5,73.25 51,73.25 53.5,73.25 56,73.25 58.5,73.25 61,73.25
pads on no net: CN1.A21 CN1.A22 CN1.A23 CN1.A24 CN1.A53 CN1.A54
copper on no net: | length 27.6
  TOP w0.3: 61.5,19.05 61.5,23.645 ; 62.5,19.05 62.5,23.645 ; 91.5,19.05 91.5,23.645 ; 92.5,19.05 92.5,23.645 ; 93.5,19.05 93.5,23.645 ; 94.5,19.05 94.5,23.645

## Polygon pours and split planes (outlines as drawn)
no net on TOP "TOP18" (solid, pour order 49): 119.15,21 119.15,25.85 129,25.85 129,21
no net on TOP "TOP17" (solid, pour order 48): 131,21 131,25.936 ccw(c130.5,27.35) 131,28.764 131,56.595 ccw(c130.475,58) 131.975,58 131.975,59.2 ccw(c130.475,59.2) 131,60.605 131,71.586 ccw(c130.5,73) 132,73 132,74.2 ccw(c130.5,74.2) 131,75.614 131,83 139,83 139,21
no net on TOP "TOP16" (solid, pour order 47): 11,21 11,83 19,83 19,75.614 ccw(c19.5,74.2) 18,74.2 18,73 ccw(c19.5,73) 19,71.586 19,60.605 ccw(c19.525,59.2) 18.025,59.2 18.025,58 ccw(c19.525,58) 19,56.595 19,28.764 ccw(c19.5,27.35) 19,25.936 19,21
no net on TOP "TOP15" (solid, pour order 46): 21,21 21,25.85 30.85,25.85 30.85,21
N12556338 on TOP "TOP14" (solid, pour order 45): 64.5,49.75 cw(c64.5,49.8) 64.45,49.8 64.45,58.3 cw(c64.5,58.3) 64.5,58.35 67.779,58.35 cw(c67.779,58.3) 67.815,58.335 68.035,58.115 cw(c68,58.079) 68.05,58.079 68.05,49.8 cw(c68,49.8) 68,49.75
N12552974 on TOP "TOP13" (solid, pour order 44): 25.05,31.5 cw(c25.05,31.55) 25,31.55 25,81.079 cw(c25.05,81.079) 25.015,81.115 25.485,81.585 cw(c25.521,81.55) 25.521,81.6 30.329,81.6 cw(c30.329,81.55) 30.365,81.585 30.535,81.415 cw(c30.5,81.379) 30.55,81.379 30.55,76.512 cw(c30.5,76.512) 30.508,76.462 ccw(c31,73.25) 31,70 67.879,70 cw(c67.879,69.95) 67.915,69.985 68.385,69.515 cw(c68.35,69.479) 68.4,69.479 68.4,59.721 cw(c68.35,59.721) 68.385,59.685 68.065,59.365 cw(c68.029,59.4) 68.029,59.35 62.75,59.35 62.25,58.85 62.25,49.771 cw(c62.2,49.771) 62.235,49.735 61.965,49.465 cw(c61.929,49.5) 61.929,49.45 61.35,49.45 ccw(c61.35,46.6) 59.902,49.055 cw(c59.876,49.098) 59.879,49.048 ccw(c59.957,47.686) 58.593,47.686 58.593,47.329 cw(c58.543,47.329) 58.592,47.317 ccw(c61.35,46.6) 58.536,47.049 cw(c58.486,47.057) 58.522,47.022 58.5,47 58.5,36.6 cw(c58.45,36.6) 58.45,36.55 52.8,36.55 47.765,31.515 cw(c47.729,31.55) 47.729,31.5
N12556383 on TOP "TOP12" (solid, pour order 43): 88.218,37.85 ccw(c87.8,37.775) 88.2,37.919 88.2,38.25 ccw(c87.45,38.25) 87.98,38.78 87.813,38.947 ccw(c87,38.7) 86.6,39.45 85.362,39.45 cw(c85.362,39.5) 85.339,39.456 ccw(c84.95,38.7) 84.512,39.429 cw(c84.487,39.472) 84.487,39.422 cw(c84.487,39.472) 84.47,39.425 ccw(c84.325,39.025) 84.325,39.45 83.45,39.45 ccw(c83.45,38.7) 83.189,39.403 cw(c83.172,39.45) 83.172,39.4 80.4,39.4 cw(c80.4,39.45) 80.35,39.45 80.35,47.079 cw(c80.4,47.079) 80.365,47.115 82.035,48.785 cw(c82.071,48.75) 82.048,48.795 cw(c82.071,48.75) 82.071,48.8 90.279,48.8 cw(c90.279,48.75) 90.315,48.785 90.535,48.565 cw(c90.5,48.529) 90.55,48.529 90.55,39.05 90.95,38.65 91.9,38.65 cw(c91.9,38.6) 91.95,38.6 91.95,37.9 cw(c91.9,37.9) 91.9,37.85
PGND on TOP "TOP11" (solid, pour order 42): 95.2,32.5 cw(c95.2,32.55) 95.15,32.55 95.15,37.129 cw(c95.2,37.129) 95.165,37.165 95.335,37.335 cw(c95.371,37.3) 95.371,37.35 96.1,37.35 ccw(c96.1,37.775) 96.525,37.775 96.525,38.725 ccw(c96.1,38.725) 96.1,39.15 93.271,39.15 cw(c93.271,39.2) 93.235,39.165 92.765,39.635 cw(c92.8,39.671) 92.75,39.671 92.75,48.9 92.45,49.2 78.698,49.2 cw(c78.698,49.25) 78.677,49.204 ccw(c77.525,46.625) 77.832,49.433 cw(c77.838,49.483) 77.802,49.448 77.765,49.485 cw(c77.8,49.521) 77.75,49.521 77.75,50.775 ccw(c77.325,50.775) 77.325,51.2 74.675,51.2 ccw(c74.675,50.775) 74.25,50.775 74.25,49.721 cw(c74.2,49.721) 74.235,49.685 74.015,49.465 cw(c73.979,49.5) 73.979,49.45 71.8,49.45 cw(c71.8,49.5) 71.75,49.5 71.75,57.55 71.415,57.885 cw(c71.45,57.921) 71.4,57.921 71.4,69.479 cw(c71.45,69.479) 71.415,69.515 71.885,69.985 cw(c71.921,69.95) 71.921,70 124.479,70 cw(c124.479,69.95) 124.515,69.985 124.985,69.515 cw(c124.95,69.479) 125,69.479 125,32.55 cw(c124.95,32.55) 124.95,32.5
N12552974 on TOP "TOP10" (solid, pour order 41): 34.2,21.7 cw(c34.2,21.75) 34.15,21.75 34.15,26 33.865,26.285 cw(c33.9,26.321) 33.85,26.321 33.85,29.35 32.85,30.35 25.521,30.35 cw(c25.521,30.4) 25.485,30.365 25.015,30.835 cw(c25.05,30.871) 25,30.871 25,33.95 cw(c25.05,33.95) 25.05,34 49.8,34 cw(c49.8,33.95) 49.85,33.95 49.85,21.75 cw(c49.8,21.75) 49.8,21.7
MIDPOINT on TOP "TOP9" (solid, pour order 40): 64.421,27.05 cw(c64.421,27.1) 64.409,27.051 cw(c64.421,27.1) 64.385,27.135 65.235,27.985 cw(c65.271,27.95) 65.248,27.995 cw(c65.271,27.95) 65.271,28 69.75,28 70.95,29.2 70.95,32.55 69.215,34.285 cw(c69.25,34.321) 69.2,34.321 69.2,35.8 cw(c69.25,35.8) 69.25,35.85 77.5,35.85 cw(c77.5,35.8) 77.55,35.8 77.55,34.425 cw(c77.5,34.425) 77.548,34.412 ccw(c80.45,33.65) 77.45,33.65 77.45,31.717 cw(c77.4,31.717) 77.44,31.687 ccw(c80.05,29.75) 77.103,28.379 cw(c77.058,28.358) 77.107,28.368 ccw(c80.05,28.95) 77.443,27.465 cw(c77.4,27.44) 77.45,27.44 77.45,27.1 cw(c77.4,27.1) 77.4,27.05
MIDPOINT on TOP "TOP8" (solid, pour order 39): 69.25,35 cw(c69.25,35.05) 69.2,35.05 69.2,37.5 cw(c69.25,37.5) 69.25,37.55 77.5,37.55 cw(c77.5,37.5) 77.55,37.5 77.55,35.05 cw(c77.5,35.05) 77.5,35
MIDPOINT on TOP "TOP7" (solid, pour order 38): 63.2,21.7 cw(c63.2,21.75) 63.15,21.75 63.15,25.879 cw(c63.2,25.879) 63.165,25.915 65.235,27.985 cw(c65.271,27.95) 65.271,28 69.75,28 70.235,28.485 cw(c70.271,28.45) 70.271,28.5 77.05,28.5 77.106,28.373 ccw(c80.05,28.95) 77.85,26.91 77.85,21.75 cw(c77.8,21.75) 77.8,21.7
LS_GATE on TOP "TOP6" (solid, pour order 37): 87.2,21.7 cw(c87.2,21.75) 87.15,21.75 87.15,26.85 86.265,27.735 cw(c86.3,27.771) 86.25,27.771 86.25,29.55 cw(c86.3,29.55) 86.3,29.6 89.9,29.6 cw(c89.9,29.55) 89.95,29.55 89.95,28.35 cw(c89.9,28.35) 89.9,28.3 89.421,28.3 ccw(c89.421,27.95) 89.173,28.197 88.953,27.977 ccw(c89.2,27.729) 88.85,27.729 88.85,21.75 cw(c88.8,21.75) 88.8,21.7
MIDPOINT on TOP "TOP5" (solid, pour order 36): 69.25,36.55 cw(c69.25,36.6) 69.2,36.6 69.2,38.55 68.75,39 cw(c68.785,39.036) 68.739,39.017 ccw(c67.95,38.7) 67.561,39.456 cw(c67.538,39.5) 67.538,39.45 66.312,39.45 cw(c66.312,39.5) 66.29,39.455 66.289,39.456 ccw(c65.9,38.7) 65.511,39.456 65.51,39.455 cw(c65.488,39.5) 65.488,39.45 64.4,39.45 ccw(c64.4,38.7) 64.139,39.403 cw(c64.122,39.45) 64.122,39.4 61.35,39.4 cw(c61.35,39.45) 61.3,39.45 61.3,46.479 cw(c61.35,46.479) 61.315,46.515 61.435,46.635 cw(c61.471,46.6) 61.471,46.65 65.8,46.65 cw(c65.8,46.6) 65.85,46.6 65.85,45.675 ccw(c66.275,45.675) 66.275,45.25 68.025,45.25 ccw(c68.025,45.675) 68.45,45.675 68.45,46.6 cw(c68.5,46.6) 68.5,46.65 77.5,46.65 cw(c77.5,46.6) 77.55,46.6 77.55,36.6 cw(c77.5,36.6) 77.5,36.55
PGND on TOP "TOP4" (solid, pour order 35): 95.2,21.7 cw(c95.2,21.75) 95.15,21.75 95.15,32.95 cw(c95.2,32.95) 95.2,33 124.95,33 cw(c124.95,32.95) 125,32.95 125,30.871 cw(c124.95,30.871) 124.985,30.835 124.515,30.365 cw(c124.479,30.4) 124.479,30.35 117.15,30.35 116.15,29.35 116.15,26.321 cw(c116.1,26.321) 116.135,26.285 115.85,26 115.85,21.75 cw(c115.8,21.75) 115.8,21.7 107.2,21.7 cw(c107.2,21.75) 107.15,21.75 107.15,26 106.965,26.185 cw(c107,26.221) 106.95,26.221 106.95,27.45 ccw(c105,27.45) 103.05,27.45 103.05,26.221 cw(c103,26.221) 103.035,26.185 102.85,26 102.85,21.75 cw(c102.8,21.75) 102.8,21.7
0VA on TOP "TOP3" (solid, pour order 34): 89.2,21.7 cw(c89.2,21.75) 89.15,21.75 89.15,27.729 cw(c89.2,27.729) 89.165,27.765 89.385,27.985 cw(c89.421,27.95) 89.421,28 90.879,28 cw(c90.879,27.95) 90.915,27.985 91.085,27.815 cw(c91.05,27.779) 91.1,27.779 91.1,26.321 cw(c91.05,26.321) 91.085,26.285 90.85,26.05 90.85,21.75 cw(c90.8,21.75) 90.8,21.7
0VB on TOP "TOP2" (solid, pour order 33): 59.25,21.7 cw(c59.25,21.75) 59.2,21.75 59.2,26.029 cw(c59.25,26.029) 59.215,26.065 61.135,27.985 cw(c61.171,27.95) 61.171,28 62.529,28 cw(c62.529,27.95) 62.565,27.985 62.785,27.765 cw(c62.75,27.729) 62.8,27.729 62.8,26.371 cw(c62.75,26.371) 62.785,26.335 62.565,26.115 cw(c62.529,26.15) 62.529,26.1 61,26.1 60.85,25.95 60.85,21.75 cw(c60.8,21.75) 60.8,21.7
HS_GATE on TOP "TOP1" (solid, pour order 32): 57.2,21.7 cw(c57.2,21.75) 57.15,21.75 57.15,26.429 cw(c57.2,26.429) 57.165,26.465 60.385,29.685 cw(c60.421,29.65) 60.421,29.7 67.25,29.7 cw(c67.25,29.65) 67.3,29.65 67.3,28.45 cw(c67.25,28.45) 67.25,28.4 60.95,28.4 60.401,27.851 60.4,27.85 59.95,27.4 59.949,27.399 58.85,26.3 58.85,21.75 cw(c58.8,21.75) 58.8,21.7
no net on Mid-Layer 1 "MID132" (solid, pour order 31): 131,21 131,25.936 ccw(c130.5,27.35) 131,28.764 131,56.595 ccw(c130.475,58) 131.975,58 131.975,59.2 ccw(c130.475,59.2) 131,60.605 131,71.586 ccw(c130.5,73) 132,73 132,74.2 ccw(c130.5,74.2) 131,75.614 131,83 139,83 139,21
no net on Mid-Layer 1 "MID131" (solid, pour order 30): 119.15,21 119.15,25.85 129,25.85 129,21
no net on Mid-Layer 1 "MID130" (solid, pour order 29): 21,21 21,25.85 30.85,25.85 30.85,21
no net on Mid-Layer 1 "MID129" (solid, pour order 28): 11,21 11,83 19,83 19,75.614 ccw(c19.5,74.2) 18,74.2 18,73 ccw(c19.5,73) 19,71.586 19,60.605 ccw(c19.525,59.2) 18.025,59.2 18.025,58 ccw(c19.525,58) 19,56.595 19,28.764 ccw(c19.5,27.35) 19,25.936 19,21
N12556383 on Mid-Layer 1 "MID128" (solid, pour order 27): 79.15,49.45 78.021,49.45 cw(c78.021,49.5) 77.985,49.465 77.765,49.685 cw(c77.8,49.721) 77.75,49.721 77.75,50.15 ccw(c76.9,50.15) 76.9,51 75.062,51 cw(c75.05,51.049) 75.052,50.999 ccw(c75.1,50.15) 74.25,50.15 74.25,49.721 cw(c74.2,49.721) 74.235,49.685 74.015,49.465 cw(c73.979,49.5) 74.002,49.455 cw(c73.979,49.5) 73.979,49.45 72.371,49.45 cw(c72.371,49.5) 72.335,49.465 72.115,49.685 cw(c72.15,49.721) 72.1,49.721 72.1,51.049 72.1,51.05 72.1,51.3 72.1,51.301 72.1,51.429 cw(c72.15,51.429) 72.115,51.465 72.116,51.466 74.135,53.485 cw(c74.171,53.45) 74.148,53.495 cw(c74.171,53.45) 74.171,53.5 83.2,53.5 cw(c83.2,53.45) 83.25,53.45 83.25,52.571 cw(c83.2,52.571) 83.235,52.535 81.35,50.65 81.35,47.371 cw(c81.3,47.371) 81.349,47.359 cw(c81.3,47.371) 81.265,47.335
PGND on Mid-Layer 1 "MID127" (solid, pour order 26): 269 vertices, not listed, extent 25,21.7 125,81.6
N12556383 on Mid-Layer 1 "MID126" (solid, pour order 25): 90.85,34.85 cw(c90.85,34.9) 90.8,34.9 90.8,36.629 cw(c90.85,36.629) 90.815,36.665 91.385,37.235 cw(c91.421,37.2) 91.421,37.25 93.1,37.25 cw(c93.1,37.2) 93.15,37.2 93.15,36.65 94.685,35.115 cw(c94.65,35.079) 94.7,35.079 94.7,34.9 cw(c94.65,34.9) 94.65,34.85
N12556383 on Mid-Layer 1 "MID125" (solid, pour order 24): 91.221,31.6 cw(c91.221,31.65) 91.185,31.615 90.815,31.985 cw(c90.85,32.021) 90.8,32.021 90.8,35.079 cw(c90.85,35.079) 90.815,35.115 91.185,35.485 cw(c91.221,35.45) 91.221,35.5 94.279,35.5 cw(c94.279,35.45) 94.315,35.485 94.685,35.115 cw(c94.65,35.079) 94.7,35.079 94.7,32.021 cw(c94.65,32.021) 94.685,31.985 94.315,31.615 cw(c94.279,31.65) 94.279,31.6
MIDPOINT on Mid-Layer 1 "MID124" (solid, pour order 23): 63.2,21.7 cw(c63.2,21.75) 63.15,21.75 63.15,25.879 cw(c63.2,25.879) 63.165,25.915 64.385,27.135 65.235,27.985 cw(c65.271,27.95) 65.271,28 69.75,28 70.235,28.485 70.236,28.486 70.95,29.2 70.95,32.55 69.215,34.285 cw(c69.25,34.321) 69.2,34.321 69.2,38.55 68.75,39 cw(c68.785,39.036) 68.739,39.017 ccw(c67.95,38.7) 67.95,39.55 64.221,39.55 cw(c64.221,39.6) 64.185,39.565 63.865,39.885 cw(c63.9,39.921) 63.85,39.921 63.85,46.279 cw(c63.9,46.279) 63.865,46.315 64.185,46.635 cw(c64.221,46.6) 64.221,46.65 77.5,46.65 cw(c77.5,46.6) 77.55,46.6 77.55,34.425 cw(c77.5,34.425) 77.548,34.412 ccw(c80.45,33.65) 77.45,33.65 77.45,31.717 cw(c77.4,31.717) 77.445,31.694 cw(c77.4,31.717) 77.44,31.686 ccw(c80.05,29.75) 77.063,28.47 77.103,28.379 cw(c77.058,28.358) 77.107,28.367 ccw(c80.05,28.95) 77.443,27.465 ccw(c80.05,28.95) 77.837,26.925 cw(c77.8,26.891) 77.845,26.913 cw(c77.8,26.891) 77.85,26.891 77.85,21.75 cw(c77.8,21.75) 77.8,21.7
0VA on Mid-Layer 1 "MID123" (solid, pour order 22): 83.2,21.7 cw(c83.2,21.75) 83.15,21.75 83.15,25.6 83,25.75 82.271,25.75 cw(c82.271,25.8) 82.235,25.765 80.915,27.085 cw(c80.95,27.121) 80.9,27.121 80.9,29.746 ccw(c80.05,29.75) 80.286,30.567 cw(c80.3,30.615) 80.25,30.615 80.25,33.729 cw(c80.3,33.729) 80.265,33.765 80.35,33.85 80.35,38.95 cw(c80.4,38.95) 80.4,39 83.172,39 ccw(c83.172,39.45) 83.328,39.028 cw(c83.45,38.7) 83.45,39.05 84.321,39.05 cw(c84.321,39) 84.337,39.047 ccw(c84.487,39.472) 84.718,39.086 cw(c84.95,38.7) 85.156,39.1 85.157,39.1 ccw(c85.362,39.5) 85.362,39.05 86.588,39.05 ccw(c86.588,39.5) 86.794,39.1 cw(c87,38.7) 87.418,38.868 ccw(c87.835,39.036) 87.516,38.718 cw(c87.482,38.682) 87.518,38.716 87.835,38.399 cw(c87.8,38.364) 87.85,38.364 87.85,36.5 88.3,36.05 89.279,36.05 cw(c89.279,36) 89.315,36.035 90.385,34.965 cw(c90.35,34.929) 90.4,34.929 90.4,29.671 ccw(c90.85,29.671) 90.532,29.353 90.903,28.982 ccw(c91.221,29.3) 91.067,28.877 cw(c91.05,28.83) 91.1,28.83 91.1,26.321 cw(c91.05,26.321) 91.099,26.309 cw(c91.05,26.321) 91.085,26.285 91.084,26.284 90.85,26.05 90.85,21.75 cw(c90.8,21.75) 90.8,21.7
N12552974 on Mid-Layer 1 "MID122" (solid, pour order 21): 50.55,36.55 cw(c50.55,36.6) 50.5,36.6 50.5,46.6 cw(c50.55,46.6) 50.55,46.65 58.45,46.65 cw(c58.45,46.6) 58.5,46.6 58.5,36.6 cw(c58.45,36.6) 58.45,36.55
0VB on Mid-Layer 1 "MID121" (solid, pour order 20): 43.971,48.55 cw(c43.971,48.6) 43.935,48.565 43.565,48.935 cw(c43.6,48.971) 43.55,48.971 43.55,52.029 cw(c43.6,52.029) 43.565,52.065 43.935,52.435 cw(c43.971,52.4) 43.971,52.45 47.029,52.45 cw(c47.029,52.4) 47.065,52.435 47.435,52.065 cw(c47.4,52.029) 47.45,52.029 47.45,48.971 cw(c47.4,48.971) 47.435,48.935 47.065,48.565 cw(c47.029,48.6) 47.029,48.55
0VB on Mid-Layer 1 "MID120" (solid, pour order 19): 55.2,21.7 cw(c55.2,21.75) 55.15,21.75 55.15,32.129 cw(c55.2,32.129) 55.165,32.165 57.885,34.885 cw(c57.921,34.85) 57.921,34.9 59.928,34.9 59.929,34.9 59.985,34.9 59.986,34.9 60,34.9 cw(c60.008,34.851) 60.006,34.901 ccw(c59.957,36.256) 61.314,36.256 61.314,39.1 cw(c61.364,39.1) 61.364,39.15 67.95,39.15 cw(c67.95,38.7) 68.367,38.868 68.368,38.868 68.37,38.862 68.37,38.861 ccw(c68.785,39.036) 68.467,38.717 68.785,38.399 cw(c68.75,38.364) 68.8,38.364 68.8,36.821 cw(c68.75,36.821) 68.785,36.785 67.8,35.8 67.8,32.821 cw(c67.75,32.821) 67.785,32.785 67.3,32.3 67.3,28.45 cw(c67.25,28.45) 67.25,28.4 65.05,28.4 62.75,26.1 62.75,21.75 cw(c62.7,21.75) 62.7,21.7
N12556383 on Mid-Layer 1 "MID119" (solid, pour order 18): 95.821,55.25 cw(c95.821,55.3) 95.785,55.265 95.565,55.485 cw(c95.6,55.521) 95.55,55.521 95.55,56.125 cw(c95.6,56.125) 95.551,56.136 ccw(c93.991,56.491) 93.636,58.051 cw(c93.625,58.1) 93.625,58.05 93.021,58.05 cw(c93.021,58.1) 92.985,58.065 92.765,58.285 cw(c92.8,58.321) 92.75,58.321 92.75,61.379 cw(c92.8,61.379) 92.765,61.415 92.985,61.635 cw(c93.021,61.6) 93.021,61.65 93.625,61.65 cw(c93.625,61.6) 93.636,61.649 ccw(c93.991,63.209) 95.551,63.564 cw(c95.6,63.575) 95.55,63.575 95.55,64.129 cw(c95.6,64.129) 95.565,64.165 95.835,64.435 cw(c95.871,64.4) 95.871,64.45 98.879,64.45 cw(c98.879,64.4) 98.915,64.435 99.135,64.215 cw(c99.1,64.179) 99.15,64.179 99.15,63.575 cw(c99.1,63.575) 99.149,63.564 ccw(c100.709,63.209) 101.064,61.649 cw(c101.075,61.6) 101.075,61.65 101.679,61.65 cw(c101.679,61.6) 101.715,61.635 101.935,61.415 cw(c101.9,61.379) 101.95,61.379 101.95,58.371 cw(c101.9,58.371) 101.935,58.335 101.665,58.065 cw(c101.629,58.1) 101.629,58.05 101.075,58.05 cw(c101.075,58.1) 101.064,58.051 ccw(c100.709,56.491) 99.149,56.136 cw(c99.1,56.125) 99.15,56.125 99.15,55.521 cw(c99.1,55.521) 99.135,55.485 98.915,55.265 cw(c98.879,55.3) 98.879,55.25
no net on Mid-Layer 2 "MID240" (solid, pour order 17): 131,21 131,25.936 ccw(c130.5,27.35) 131,28.764 131,56.595 ccw(c130.475,58) 131.975,58 131.975,59.2 ccw(c130.475,59.2) 131,60.605 131,71.586 ccw(c130.5,73) 132,73 132,74.2 ccw(c130.5,74.2) 131,75.614 131,83 139,83 139,21
no net on Mid-Layer 2 "MID239" (solid, pour order 16): 119.15,21 119.15,25.85 129,25.85 129,21
no net on Mid-Layer 2 "MID238" (solid, pour order 15): 21,21 21,25.85 30.85,25.85 30.85,21
no net on Mid-Layer 2 "MID237" (solid, pour order 14): 11,21 11,83 19,83 19,75.614 ccw(c19.5,74.2) 18,74.2 18,73 ccw(c19.5,73) 19,71.586 19,60.605 ccw(c19.525,59.2) 18.025,59.2 18.025,58 ccw(c19.525,58) 19,56.595 19,28.764 ccw(c19.5,27.35) 19,25.936 19,21
0VA on Mid-Layer 2 "MID236" (solid, pour order 13): 85.85,36.75 cw(c85.85,36.8) 85.8,36.8 85.8,37.3 ccw(c84.95,37.3) 84.95,38.15 84.721,38.15 cw(c84.721,38.2) 84.685,38.165 84.515,38.335 cw(c84.55,38.371) 84.5,38.371 84.5,38.929 cw(c84.55,38.929) 84.515,38.965 84.685,39.135 cw(c84.721,39.1) 84.721,39.15 91.129,39.15 cw(c91.129,39.1) 91.165,39.065 91.164,39.064 88.865,36.765 cw(c88.829,36.8) 88.829,36.75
